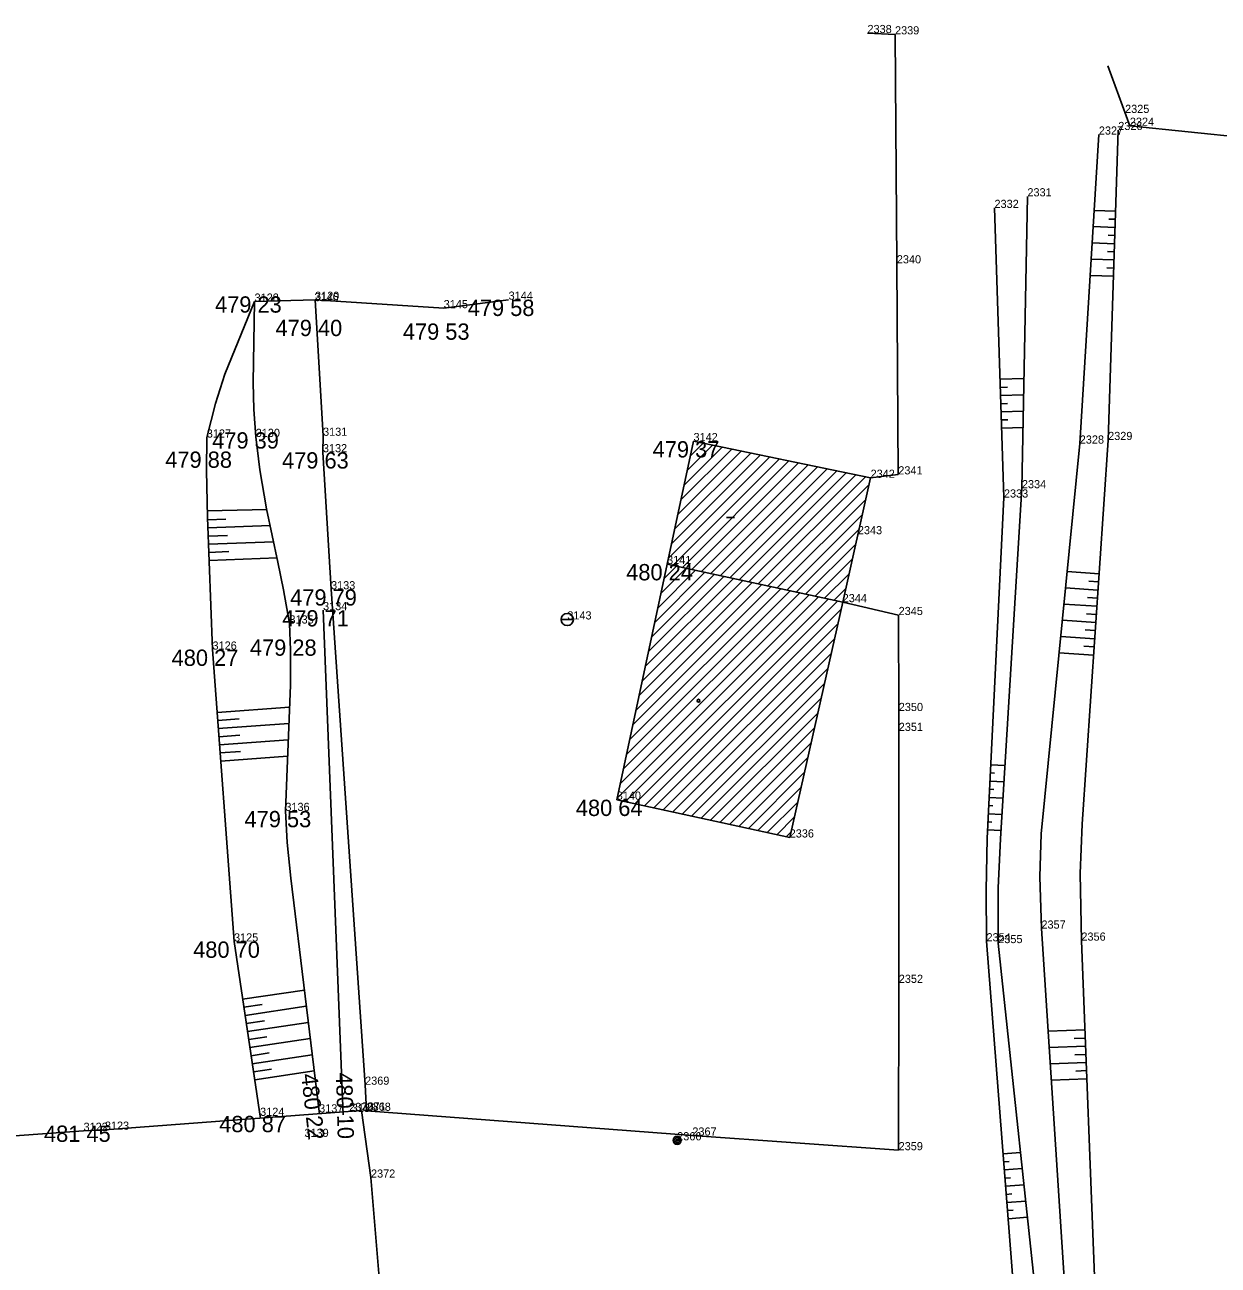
# Model space of a CAD drawing. Extents: x -559180 to -551373, y -1076947 to -1072071.
# Drawn here: x -553654.3 to -553581.2, y -1076239.4 to -1076163.3 of the extents above; entities that cross this region are included whole.
import ezdxf

# ---------------------------------------------------------------- set-up
doc = ezdxf.new("R2010")
doc.units = 0
for name, color, linetype in [('12_PLOTY', 7, 'Continuous'), ('14_BUDOVY', 7, 'Continuous'), ('1_VODA_ZN', 7, 'Continuous'), ('20_EL_ZN', 7, 'Continuous'), ('26_SRAFY', 7, 'Continuous'), ('27_HRANA_PATA', 7, 'Continuous'), ('28_VODA', 7, 'Continuous'), ('32', 7, 'Continuous'), ('3_BODY', 7, 'Continuous'), ('47_ZN_STAV_OBJ$', 7, 'Continuous'), ('6_VYSKY', 7, 'Continuous')]:
    doc.layers.add(name, color=color, linetype=linetype)

# ---------------------------------------------------------------- blocks, each defined once
blk = doc.blocks.new('POINT_DISPLAY')
blk.add_line((0, 0), (0, 0))
blk = doc.blocks.new('ST')
at = {"layer": '1_VODA_ZN'}
blk.add_line((-0.375, 0), (0.375, 0), dxfattribs=at)
blk.add_circle((0, 0), 0.375, dxfattribs=at)
blk = doc.blocks.new('BZ')
at = {"layer": '47_ZN_STAV_OBJ$'}
blk.add_circle((0, 0), 0.0875, dxfattribs=at)
blk = doc.blocks.new('BD')
at = {"layer": '47_ZN_STAV_OBJ$'}
blk.add_line((-0.25, 0), (0.25, 0), dxfattribs=at)
blk = doc.blocks.new('SLB')
at = {"layer": '20_EL_ZN'}
for radius in [0.25, 0.158, 0.05]:
    blk.add_circle((0, 0), radius, dxfattribs=at)

msp = doc.modelspace()

# ---------------------------------------------------------------- linework, layer by layer
at = {"layer": '12_PLOTY'}
for p, q in [((-553602.66, -1076163.76), (-553600.97, -1076163.84)), ((-553600.97, -1076163.84), (-553600.86, -1076177.89)), ((-553586.57, -1076169.45), (-553587.924, -1076165.76)), ((-553574.77, -1076170.67), (-553586.57, -1076169.45)), ((-553600.86, -1076177.89), (-553600.77, -1076190.84)), ((-553640.25, -1076180.24), (-553636.54, -1076180.13)), ((-553636.05, -1076188.47), (-553636.54, -1076180.13)), ((-553636.54, -1076180.13), (-553628.65, -1076180.64)), ((-553628.65, -1076180.64), (-553624.67, -1076180.12)), ((-553636.05, -1076188.47), (-553636.06, -1076189.48)), ((-553635.56, -1076197.89), (-553636.06, -1076189.48)), ((-553600.77, -1076190.84), (-553602.47, -1076191.05)), ((-553633.47, -1076228.29), (-553635.56, -1076197.89)), ((-553634.824, -1076230.128), (-553636.05, -1076199.17)), ((-553604.18, -1076198.68), (-553600.75, -1076199.47)), ((-553600.75, -1076199.47), (-553600.74, -1076205.36)), ((-553600.74, -1076205.36), (-553600.74, -1076206.58)), ((-553600.74, -1076206.58), (-553600.74, -1076222.04)), ((-553600.74, -1076222.04), (-553600.75, -1076232.31)), ((-553633.38, -1076229.89), (-553633.47, -1076228.29)), ((-553649.43, -1076231.05), (-553633.69, -1076229.87)), ((-553633.69, -1076229.87), (-553633.11, -1076233.99)), ((-553613.4, -1076231.41), (-553633.38, -1076229.89)), ((-553670.67, -1076232.55), (-553650.74, -1076231.12)), ((-553650.74, -1076231.12), (-553649.43, -1076231.05)), ((-553600.75, -1076232.31), (-553613.4, -1076231.41)), ((-553633.11, -1076233.99), (-553632.13, -1076245.91))]:
    msp.add_line(p, q, dxfattribs=at)
at = {"layer": '14_BUDOVY'}
for p, q in [((-553614.95, -1076196.34), (-553613.33, -1076188.8)), ((-553602.47, -1076191.05), (-553613.33, -1076188.8)), ((-553602.47, -1076191.05), (-553604.18, -1076198.68)), ((-553618.04, -1076210.8), (-553614.95, -1076196.34)), ((-553604.18, -1076198.68), (-553614.95, -1076196.34)), ((-553607.43, -1076213.12), (-553604.18, -1076198.68)), ((-553607.43, -1076213.12), (-553618.04, -1076210.8))]:
    msp.add_line(p, q, dxfattribs=at)
at = {"layer": '26_SRAFY'}
for p, q in [((-553588.757, -1076174.64), (-553587.442, -1076174.683)), ((-553588.818, -1076175.638), (-553587.475, -1076175.682)), ((-553587.857, -1076175.169), (-553587.458, -1076175.182)), ((-553587.898, -1076176.169), (-553587.491, -1076176.182)), ((-553588.88, -1076176.637), (-553587.507, -1076176.682)), ((-553587.94, -1076177.168), (-553587.524, -1076177.181)), ((-553588.941, -1076177.635), (-553587.54, -1076177.681)), ((-553589.003, -1076178.634), (-553587.572, -1076178.681)), ((-553587.981, -1076178.167), (-553587.556, -1076178.181)), ((-553593.062, -1076184.955), (-553594.527, -1076185.002)), ((-553594.079, -1076185.488), (-553594.511, -1076185.502)), ((-553593.081, -1076185.956), (-553594.494, -1076186.002)), ((-553594.062, -1076186.488), (-553594.478, -1076186.502)), ((-553593.1, -1076186.957), (-553594.462, -1076187.001)), ((-553594.045, -1076187.488), (-553594.445, -1076187.501)), ((-553593.119, -1076187.958), (-553594.429, -1076188.001)), ((-553639.481, -1076192.987), (-553643.148, -1076193.073)), ((-553642.007, -1076193.584), (-553643.133, -1076193.627)), ((-553639.278, -1076193.981), (-553643.114, -1076194.127)), ((-553641.919, -1076194.582), (-553643.095, -1076194.627)), ((-553639.075, -1076194.974), (-553643.076, -1076195.126)), ((-553641.832, -1076195.58), (-553643.057, -1076195.626)), ((-553638.872, -1076195.968), (-553643.038, -1076196.126)), ((-553590.415, -1076196.803), (-553588.455, -1076196.935)), ((-553589.081, -1076197.394), (-553588.489, -1076197.434)), ((-553590.513, -1076197.798), (-553588.522, -1076197.933)), ((-553589.158, -1076198.391), (-553588.556, -1076198.432)), ((-553590.611, -1076198.794), (-553588.59, -1076198.931)), ((-553590.709, -1076199.79), (-553588.657, -1076199.929)), ((-553589.235, -1076199.388), (-553588.624, -1076199.43)), ((-553590.808, -1076200.785), (-553588.725, -1076200.926)), ((-553589.311, -1076200.385), (-553588.691, -1076200.427)), ((-553589.388, -1076201.383), (-553588.759, -1076201.425)), ((-553590.906, -1076201.781), (-553588.792, -1076201.924)), ((-553638.102, -1076205.112), (-553642.546, -1076205.439)), ((-553641.193, -1076205.841), (-553642.51, -1076205.938)), ((-553638.143, -1076206.118), (-553642.473, -1076206.437)), ((-553641.154, -1076206.841), (-553642.436, -1076206.935)), ((-553638.183, -1076207.123), (-553642.399, -1076207.434)), ((-553641.115, -1076207.841), (-553642.363, -1076207.933)), ((-553638.224, -1076208.129), (-553642.326, -1076208.431)), ((-553594.867, -1076209.172), (-553595.125, -1076209.16)), ((-553594.232, -1076208.703), (-553595.101, -1076208.66)), ((-553594.293, -1076209.701), (-553595.15, -1076209.659)), ((-553594.355, -1076210.7), (-553595.2, -1076210.658)), ((-553594.92, -1076210.171), (-553595.175, -1076210.158)), ((-553594.973, -1076211.17), (-553595.224, -1076211.157)), ((-553595.025, -1076212.168), (-553595.274, -1076212.156)), ((-553594.416, -1076211.698), (-553595.249, -1076211.657)), ((-553594.477, -1076212.696), (-553595.298, -1076212.655)), ((-553637.197, -1076222.479), (-553640.98, -1076223.045)), ((-553639.775, -1076223.37), (-553640.906, -1076223.539)), ((-553637.077, -1076223.472), (-553640.832, -1076224.034)), ((-553639.636, -1076224.36), (-553640.758, -1076224.528)), ((-553636.957, -1076224.465), (-553640.684, -1076225.023)), ((-553591.578, -1076225.012), (-553589.328, -1076224.925)), ((-553639.497, -1076225.351), (-553640.61, -1076225.517)), ((-553636.838, -1076225.459), (-553640.537, -1076226.012)), ((-553589.98, -1076225.451), (-553589.309, -1076225.425)), ((-553639.357, -1076226.341), (-553640.463, -1076226.506)), ((-553636.718, -1076226.452), (-553640.389, -1076227.001)), ((-553591.513, -1076226.011), (-553589.289, -1076225.924)), ((-553589.933, -1076226.45), (-553589.27, -1076226.424)), ((-553639.218, -1076227.331), (-553640.315, -1076227.495)), ((-553591.448, -1076227.009), (-553589.251, -1076226.924)), ((-553589.887, -1076227.449), (-553589.231, -1076227.423)), ((-553636.598, -1076227.445), (-553640.241, -1076227.99)), ((-553591.383, -1076228.007), (-553589.212, -1076227.923)), ((-553593.271, -1076232.44), (-553594.344, -1076232.524)), ((-553593.979, -1076232.997), (-553594.306, -1076233.022)), ((-553593.165, -1076233.435), (-553594.267, -1076233.521)), ((-553593.893, -1076233.993), (-553594.228, -1076234.019)), ((-553593.059, -1076234.429), (-553594.189, -1076234.518)), ((-553593.807, -1076234.989), (-553594.15, -1076235.016)), ((-553592.953, -1076235.424), (-553594.111, -1076235.514)), ((-553593.721, -1076235.986), (-553594.073, -1076236.013)), ((-553592.847, -1076236.419), (-553594.034, -1076236.511))]:
    msp.add_line(p, q, dxfattribs=at)
at = {"layer": '27_HRANA_PATA'}
for p, q in [((-553587.28, -1076169.71), (-553587.9, -1076188.73)), ((-553594.87, -1076174.49), (-553594.29, -1076192.26)), ((-553641.51, -1076219.5), (-553642.83, -1076201.59)), ((-553639.886, -1076230.363), (-553641.51, -1076219.5)), ((-553589.54, -1076219.45), (-553588.22, -1076253.54))]:
    msp.add_line(p, q, dxfattribs=at)
for points in [[(-553643.18, -1076188.58), (-553642.64, -1076186.497), (-553642.074, -1076184.687), (-553640.25, -1076180.24)], [(-553640.25, -1076180.24), (-553640.332, -1076185.207), (-553640.287, -1076186.859), (-553640.18, -1076188.54)], [(-553642.83, -1076201.59), (-553643.138, -1076193.487), (-553643.206, -1076190.592), (-553643.18, -1076188.58)], [(-553640.18, -1076188.54), (-553639.926, -1076190.569), (-553639.519, -1076192.945), (-553638.817, -1076196.225), (-553638.478, -1076197.922), (-553638.11, -1076199.99)], [(-553587.9, -1076188.73), (-553589.494, -1076212.301), (-553589.611, -1076215.332), (-553589.54, -1076219.45)], [(-553594.29, -1076192.26), (-553595.324, -1076213.175), (-553595.382, -1076216.352), (-553595.36, -1076219.49)], [(-553638.11, -1076199.99), (-553638.048, -1076201.632), (-553638.048, -1076203.781), (-553638.36, -1076211.49)], [(-553638.36, -1076211.49), (-553638.251, -1076213.418), (-553638.025, -1076215.613), (-553636.277, -1076230.103)], [(-553595.36, -1076219.49), (-553593.357, -1076245.196), (-553593.328, -1076248.024), (-553593.49, -1076250.56)]]:
    msp.add_lwpolyline(points, dxfattribs=at)
at = {"layer": '28_VODA'}
for p, q in [((-553588.47, -1076169.99), (-553589.64, -1076188.95)), ((-553592.85, -1076173.78), (-553593.19, -1076191.69)), ((-553591.99, -1076218.71), (-553589.75, -1076253))]:
    msp.add_line(p, q, dxfattribs=at)
for points in [[(-553589.64, -1076188.95), (-553592.001, -1076212.884), (-553592.089, -1076215.536), (-553591.99, -1076218.71)], [(-553593.19, -1076191.69), (-553594.508, -1076213.204), (-553594.654, -1076216.207), (-553594.64, -1076219.6)], [(-553594.64, -1076219.6), (-553592.045, -1076243.943), (-553591.899, -1076247.032), (-553591.96, -1076249.58)]]:
    msp.add_lwpolyline(points, dxfattribs=at)
at = {"layer": '32'}
for p, q in [((-553614.104, -1076192.402), (-553610.987, -1076189.285)), ((-553613.91, -1076191.502), (-553611.573, -1076189.164)), ((-553613.717, -1076190.601), (-553612.158, -1076189.043)), ((-553613.523, -1076189.701), (-553612.744, -1076188.921)), ((-553614.878, -1076196.005), (-553608.644, -1076189.771)), ((-553614.684, -1076195.104), (-553609.23, -1076189.649)), ((-553614.585, -1076196.419), (-553608.058, -1076189.892)), ((-553614.491, -1076194.204), (-553609.816, -1076189.528)), ((-553614.297, -1076193.303), (-553610.401, -1076189.407)), ((-553614.004, -1076196.545), (-553607.473, -1076190.014)), ((-553613.423, -1076196.672), (-553606.887, -1076190.135)), ((-553612.843, -1076196.798), (-553606.301, -1076190.256)), ((-553612.262, -1076196.924), (-553605.715, -1076190.378)), ((-553611.681, -1076197.05), (-553605.13, -1076190.499)), ((-553611.1, -1076197.177), (-553604.544, -1076190.62)), ((-553610.519, -1076197.303), (-553603.958, -1076190.742)), ((-553609.938, -1076197.429), (-553603.372, -1076190.863)), ((-553609.357, -1076197.555), (-553602.787, -1076190.984)), ((-553608.776, -1076197.681), (-553602.564, -1076191.469)), ((-553608.195, -1076197.808), (-553602.768, -1076192.38)), ((-553607.615, -1076197.934), (-553602.972, -1076193.292)), ((-553607.034, -1076198.06), (-553603.177, -1076194.203)), ((-553606.453, -1076198.186), (-553603.381, -1076195.114)), ((-553605.872, -1076198.312), (-553603.585, -1076196.026)), ((-553615.911, -1076200.836), (-553612.046, -1076196.971)), ((-553615.719, -1076199.937), (-553612.626, -1076196.845)), ((-553615.527, -1076199.038), (-553613.207, -1076196.719)), ((-553615.334, -1076198.139), (-553613.788, -1076196.592)), ((-553615.142, -1076197.239), (-553614.369, -1076196.466)), ((-553605.291, -1076198.439), (-553603.789, -1076196.937)), ((-553617.064, -1076206.232), (-553608.56, -1076197.728)), ((-553616.872, -1076205.333), (-553609.141, -1076197.602)), ((-553616.68, -1076204.433), (-553609.722, -1076197.476)), ((-553616.487, -1076203.534), (-553610.303, -1076197.35)), ((-553616.295, -1076202.635), (-553610.884, -1076197.223)), ((-553616.103, -1076201.736), (-553611.465, -1076197.097)), ((-553618.025, -1076210.728), (-553605.656, -1076198.359)), ((-553617.833, -1076209.829), (-553606.237, -1076198.233)), ((-553617.64, -1076208.93), (-553606.817, -1076198.107)), ((-553617.506, -1076210.917), (-553605.075, -1076198.486)), ((-553617.448, -1076208.031), (-553607.398, -1076197.981)), ((-553617.256, -1076207.131), (-553607.979, -1076197.855)), ((-553604.71, -1076198.565), (-553603.994, -1076197.848)), ((-553616.926, -1076211.044), (-553604.494, -1076198.612)), ((-553616.345, -1076211.171), (-553604.274, -1076199.099)), ((-553615.765, -1076211.297), (-553604.48, -1076200.012)), ((-553615.185, -1076211.424), (-553604.685, -1076200.924)), ((-553614.605, -1076211.551), (-553604.891, -1076201.837)), ((-553614.025, -1076211.678), (-553605.096, -1076202.749)), ((-553613.444, -1076211.805), (-553605.301, -1076203.662)), ((-553612.864, -1076211.932), (-553605.507, -1076204.574)), ((-553612.284, -1076212.059), (-553605.712, -1076205.487)), ((-553611.704, -1076212.186), (-553605.917, -1076206.399)), ((-553611.123, -1076212.312), (-553606.123, -1076207.312)), ((-553610.543, -1076212.439), (-553606.328, -1076208.224)), ((-553609.963, -1076212.566), (-553606.533, -1076209.137)), ((-553609.383, -1076212.693), (-553606.739, -1076210.049)), ((-553608.802, -1076212.82), (-553606.944, -1076210.962)), ((-553608.222, -1076212.947), (-553607.15, -1076211.874)), ((-553607.642, -1076213.074), (-553607.355, -1076212.787))]:
    msp.add_line(p, q, dxfattribs=at)

# ---------------------------------------------------------------- block references
at = {"layer": '1_VODA_ZN'}
for name, p in [('POINT_DISPLAY', (-553602.66, -1076163.76)), ('POINT_DISPLAY', (-553600.97, -1076163.84)), ('POINT_DISPLAY', (-553586.86, -1076168.66)), ('POINT_DISPLAY', (-553586.57, -1076169.45)), ('POINT_DISPLAY', (-553588.47, -1076169.99)), ('POINT_DISPLAY', (-553587.28, -1076169.71)), ('POINT_DISPLAY', (-553592.85, -1076173.78)), ('POINT_DISPLAY', (-553594.87, -1076174.49)), ('POINT_DISPLAY', (-553600.86, -1076177.89)), ('POINT_DISPLAY', (-553640.25, -1076180.24)), ('POINT_DISPLAY', (-553636.58, -1076180.21)), ('POINT_DISPLAY', (-553636.54, -1076180.13)), ('POINT_DISPLAY', (-553624.67, -1076180.12)), ('POINT_DISPLAY', (-553628.65, -1076180.64)), ('POINT_DISPLAY', (-553643.18, -1076188.58)), ('POINT_DISPLAY', (-553640.18, -1076188.54)), ('POINT_DISPLAY', (-553636.05, -1076188.47)), ('POINT_DISPLAY', (-553613.33, -1076188.8)), ('POINT_DISPLAY', (-553589.64, -1076188.95)), ('POINT_DISPLAY', (-553587.9, -1076188.73)), ('POINT_DISPLAY', (-553636.06, -1076189.48)), ('POINT_DISPLAY', (-553600.77, -1076190.84)), ('POINT_DISPLAY', (-553602.47, -1076191.05)), ('POINT_DISPLAY', (-553594.29, -1076192.26)), ('POINT_DISPLAY', (-553593.19, -1076191.69)), ('POINT_DISPLAY', (-553603.25, -1076194.51)), ('POINT_DISPLAY', (-553614.95, -1076196.34)), ('POINT_DISPLAY', (-553635.56, -1076197.89)), ('POINT_DISPLAY', (-553636.05, -1076199.17)), ('POINT_DISPLAY', (-553604.18, -1076198.68)), ('POINT_DISPLAY', (-553638.11, -1076199.99)), ('ST', (-553621.07, -1076199.74)), ('POINT_DISPLAY', (-553621.07, -1076199.74)), ('POINT_DISPLAY', (-553600.75, -1076199.47)), ('POINT_DISPLAY', (-553642.83, -1076201.59)), ('POINT_DISPLAY', (-553600.74, -1076205.36)), ('POINT_DISPLAY', (-553600.74, -1076206.58)), ('POINT_DISPLAY', (-553618.04, -1076210.8)), ('POINT_DISPLAY', (-553638.36, -1076211.49)), ('POINT_DISPLAY', (-553607.43, -1076213.12)), ('POINT_DISPLAY', (-553591.99, -1076218.71)), ('POINT_DISPLAY', (-553641.51, -1076219.5)), ('POINT_DISPLAY', (-553595.36, -1076219.49)), ('POINT_DISPLAY', (-553594.64, -1076219.6)), ('POINT_DISPLAY', (-553589.54, -1076219.45)), ('POINT_DISPLAY', (-553600.74, -1076222.04)), ('POINT_DISPLAY', (-553633.47, -1076228.29)), ('POINT_DISPLAY', (-553639.91, -1076230.2)), ('POINT_DISPLAY', (-553636.29, -1076229.99)), ('POINT_DISPLAY', (-553634.45, -1076229.9)), ('POINT_DISPLAY', (-553634.29, -1076229.96)), ('POINT_DISPLAY', (-553633.69, -1076229.87)), ('POINT_DISPLAY', (-553633.38, -1076229.89)), ('POINT_DISPLAY', (-553650.74, -1076231.12)), ('POINT_DISPLAY', (-553649.43, -1076231.05)), ('POINT_DISPLAY', (-553637.19, -1076231.49)), ('POINT_DISPLAY', (-553614.33, -1076231.7)), ('POINT_DISPLAY', (-553613.4, -1076231.41)), ('POINT_DISPLAY', (-553600.75, -1076232.31)), ('POINT_DISPLAY', (-553633.11, -1076233.99))]:
    msp.add_blockref(name, p, dxfattribs=at)
at = {"layer": '20_EL_ZN'}
msp.add_blockref('SLB', (-553614.33, -1076231.7), dxfattribs=at)
at = {"layer": '32'}
for p in [(-553588.47, -1076169.99), (-553613.33, -1076188.8), (-553608.442, -1076189.85), (-553614.95, -1076196.34)]:
    msp.add_blockref('POINT_DISPLAY', p, dxfattribs=at)
at = {"layer": '47_ZN_STAV_OBJ$'}
for name, p in [('BD', (-553611.065, -1076193.483)), ('BZ', (-553613.02, -1076204.725))]:
    msp.add_blockref(name, p, dxfattribs=at)

# ---------------------------------------------------------------- texts
at = {"layer": '3_BODY'}
for s, p in [('2338', (-553602.66, -1076163.76)), ('2339', (-553600.97, -1076163.84)), ('2325', (-553586.86, -1076168.66)), ('2327', (-553588.47, -1076169.99)), ('2326', (-553587.28, -1076169.71)), ('2324', (-553586.57, -1076169.45)), ('2331', (-553592.85, -1076173.78)), ('2332', (-553594.87, -1076174.49)), ('2340', (-553600.86, -1076177.89)), ('3128', (-553640.25, -1076180.24)), ('3146', (-553636.58, -1076180.21)), ('3129', (-553636.54, -1076180.13)), ('3145', (-553628.65, -1076180.64)), ('3144', (-553624.67, -1076180.12)), ('3127', (-553643.18, -1076188.58)), ('3130', (-553640.18, -1076188.54)), ('3131', (-553636.05, -1076188.47)), ('3142', (-553613.33, -1076188.8)), ('2328', (-553589.64, -1076188.95)), ('2329', (-553587.9, -1076188.73)), ('3132', (-553636.06, -1076189.48)), ('2342', (-553602.47, -1076191.05)), ('2341', (-553600.77, -1076190.84)), ('2334', (-553593.19, -1076191.69)), ('2333', (-553594.29, -1076192.26)), ('2343', (-553603.25, -1076194.51)), ('3141', (-553614.95, -1076196.34)), ('3133', (-553635.56, -1076197.89)), ('2344', (-553604.18, -1076198.68)), ('3134', (-553636.05, -1076199.17)), ('3143', (-553621.07, -1076199.74)), ('2345', (-553600.75, -1076199.47)), ('3135', (-553638.11, -1076199.99)), ('3126', (-553642.83, -1076201.59)), ('2350', (-553600.74, -1076205.36)), ('2351', (-553600.74, -1076206.58)), ('3140', (-553618.04, -1076210.8)), ('3136', (-553638.36, -1076211.49)), ('2336', (-553607.43, -1076213.12)), ('2357', (-553591.99, -1076218.71)), ('3125', (-553641.51, -1076219.5)), ('2354', (-553595.36, -1076219.49)), ('2356', (-553589.54, -1076219.45)), ('2355', (-553594.64, -1076219.6)), ('2352', (-553600.74, -1076222.04)), ('2369', (-553633.47, -1076228.29)), ('3124', (-553639.91, -1076230.2)), ('3137', (-553636.29, -1076229.99)), ('2370', (-553634.45, -1076229.9)), ('3138', (-553634.29, -1076229.96)), ('2371', (-553633.69, -1076229.87)), ('2368', (-553633.38, -1076229.89)), ('3122', (-553650.74, -1076231.12)), ('3123', (-553649.43, -1076231.05)), ('3139', (-553637.19, -1076231.49)), ('2366', (-553614.33, -1076231.7)), ('2367', (-553613.4, -1076231.41)), ('2359', (-553600.75, -1076232.31)), ('2372', (-553633.11, -1076233.99))]:
    msp.add_text(s, height=0.5, dxfattribs=at).set_placement(p)
at = {"layer": '6_VYSKY'}
for s, p in [('479 23', (-553642.673, -1076180.914)), ('479 58', (-553627.175, -1076181.12)), ('479 40', (-553638.964, -1076182.352)), ('479 53', (-553631.155, -1076182.577)), ('479 39', (-553642.848, -1076189.255)), ('479 37', (-553615.835, -1076189.8)), ('479 88', (-553645.726, -1076190.435)), ('479 63', (-553638.565, -1076190.48)), ('480 24', (-553617.455, -1076197.34)), ('479 79', (-553638.065, -1076198.89)), ('479 71', (-553638.555, -1076200.17)), ('479 28', (-553640.534, -1076201.968)), ('480 27', (-553645.335, -1076202.59)), ('480 64', (-553620.545, -1076211.8)), ('479 53', (-553640.865, -1076212.49)), ('480 70', (-553644.015, -1076220.5)), ('480 87', (-553642.415, -1076231.2)), ('481 45', (-553653.164, -1076231.794))]:
    msp.add_text(s, height=1, dxfattribs=at).set_placement(p)
for s, rotation, p in [('480 22', 276.4214, (-553637.398, -1076227.656)), ('480 10', 271.60281, (-553635.262, -1076227.543))]:
    msp.add_text(s, height=1, rotation=rotation, dxfattribs=at).set_placement(p)

doc.saveas('drawing.dxf')
